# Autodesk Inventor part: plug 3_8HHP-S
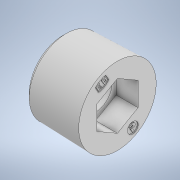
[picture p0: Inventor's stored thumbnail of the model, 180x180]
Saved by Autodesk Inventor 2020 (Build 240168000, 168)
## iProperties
Created: 2019-12
Part Number: plug 3_8HHP-S
Material: Generico
Description: STEP AP203
Document SubType Name: Modeling
Designer: carlo
Density: 1 g/cm^3
Appearance: Default
DataBaseUnit: MM
Title: p:/temp/worker_145/temp/exporttempdir_1976_32_ajvCy/format_0/Adapters Hexagon socket plug 3_8HHP-S.stp
Revision Number: NONE
Sending System: PARTsolutions
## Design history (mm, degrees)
feature "_Adapters Hexagon socket plug 3_8HHP-S"
node "Solido1"
